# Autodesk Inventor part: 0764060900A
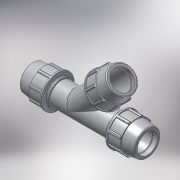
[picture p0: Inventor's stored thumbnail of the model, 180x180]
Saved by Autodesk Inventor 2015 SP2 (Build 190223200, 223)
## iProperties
Created: 2017-02
Part Number: 0764060900A
Material: PVC-Piping
Description: PLASSON 45° TEE 90-90-90
Document SubType Name: Modeling
Designer: KIM
Mass: 92.6774 g
Surface Area: 199.44 cm^2
Volume: 66.1981 cm^3
Density: 1.4 g/cm^3
Appearance: Smooth - White
Author: KIM
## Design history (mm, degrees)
derived "87640.ipt"
feature "Solid1::87640.ipt"
feature "Solid3::87640.ipt"
tag "TaggingFeature1"
body "Solid1"
other parameters: "d4" = 21.66667, "d5" = 52, "d7" = 152, "d11" = 8.66667, "d13" = 120 deg, "d14" = 117, "d15" = 8 deg, "d16" = 121.6, "d18" = 4.5, "d19" = 35 deg, "d20" = 17.5 deg, "d21" = 141.36, "d23" = 0, "d25" = 360 deg, "d27" = 3.04, "d33" = 1.8, "d42" = 62.4, "d43" = 4.56, "d46" = 2.7, "d68" = 7.8, "d91" = 106.4, "d93" = 165, "d95" = 81, "d138" = 45 deg, "d141" = 233, "d144" = 0, "d146" = 0, "d150" = 4.5, "d158" = 1.8, "d159" = 6.08, "d160" = 0, "d165" = 313.5, "d166" = 141.36, "d167" = 35 deg, "d168" = 17.5 deg, "d170" = 0, "d172" = 360 deg, "d174" = 4.56, "d177" = 3.04, "d180" = 6.08, "d181" = 0, "E_" = 152, "A_" = 233, "l_" = 165
